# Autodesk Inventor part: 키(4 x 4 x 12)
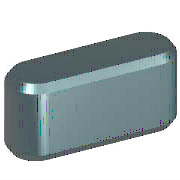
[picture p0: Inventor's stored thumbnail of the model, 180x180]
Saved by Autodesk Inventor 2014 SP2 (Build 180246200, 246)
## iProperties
IsCustomPart: 0
Created: 2009-02
Part Number: 키(4 x 4 x 12)
Material: 강, 연강
Description: 키 및 해당 키홈
Document SubType Name: Modeling
Standard: KS B 1311
Designer: KYOUNG IL JANG
Standards Organization: KS
Language: ko-KR
Size Designation: 4 x 4 x 12
Categories: <MemberInstance><Categories><Category DisplayName="샤프트 부품" InternalName="7f7aeb1f-a693-4053-b835-cee3144e0d98" Mnemonic="SHFT"><Category DisplayName="키" Interna
Density: 7.86 g/cm^3
Mass: 1.38739 g
Surface Area: 1.94869 cm^2
Volume: 0.176513 cm^3
Appearance: 강철
Author: KYOUNG IL JANG
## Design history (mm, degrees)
workplane "Work Plane1"
workplane "Work Plane2"
sketch "스케치1"
  geometry: L1 (2, 2)-(10, 2); L2 (10, -2)-(2, -2); L3 (0, 9.4)-(0, -7.4) reference; L4 (-5, 0)-(30, 0) reference; L5 (12, 0)-(12, 7); A1 r 2 centre (2, 0) between (2, 2) and (2, -2); A2 r 2 centre (10, 0) between (10, -2) and (10, 2)
  constraints: 6 end point, 5 point on circle, 4 tangent, 3 point on line, 2 centre point, 1 horizontal, 1 parallel, 1 perpendicular
  dimensions: "d0" = 2 radius of A1 (= 0.5 x PB); "d13" = 2 radius of A2 (= 0.5 x PB); "d14" = 12 distance between parallel lines of L5 L3 (= NLG)
extrude "본체1" new body sketch "스케치1" taper "d3" = 0 deg; stored distance "d4" = 10
workplane "Work Plane3"
body "Solid1"
chamfer "모따기1" distance "d8" = 0.25 (= PHH); stored, may be unused: second distance "d9" = 0.25 (= PHH), angle "d15" = 45 deg
other parameters: "d1" = -2.5 (= -PNT), "d2" = 1.5 (= PH - PNT), "NLG" = 12 [user parameter; used in 3 equation terms], "PB" = 4 [user parameter; used in 2 equation terms], "PNT" = 2.5 [user parameter; used in 2 equation terms], "PH" = 4 [user parameter; used in 1 equation term], "PHH" = 0.25 [user parameter; used in 2 equation terms], "d10" = 0, "d16" = 0, "d17" = 0, "d18" = 0, "PLB2" = 12 (= NLG) [user parameter], "WDMAX" = 12 [user parameter], "PLB1" = 12 (= NLG) [user parameter], "RR" = 0.08 [user parameter], "PUEB" = 1.8 [user parameter]
